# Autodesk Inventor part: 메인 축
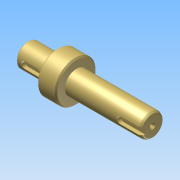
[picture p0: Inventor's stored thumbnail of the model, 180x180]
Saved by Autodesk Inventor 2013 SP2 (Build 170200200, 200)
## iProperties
Created: 2026-07
Part Number: 메인 축
Material: Generic
Document SubType Name: Modeling
Designer: aa
Density: 1 g/cm^3
Author: aa
변환 표준: STEP AP214IS
전처리기: Build: 200, Release: 2013 SP2 Update 6 - Date: Thu 07/17/2014
전송 단위: 밀리미터
불확실성: 0.01
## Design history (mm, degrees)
node "메인 축1"
node "솔리드1"
node "기준1"
